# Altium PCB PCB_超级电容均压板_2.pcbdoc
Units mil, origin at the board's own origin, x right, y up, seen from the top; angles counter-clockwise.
Board outline 2770 x 2200 mil, 2 copper layers (Top Layer, Bottom Layer); 57 components, 38 nets, 150 pads, 0 vias.
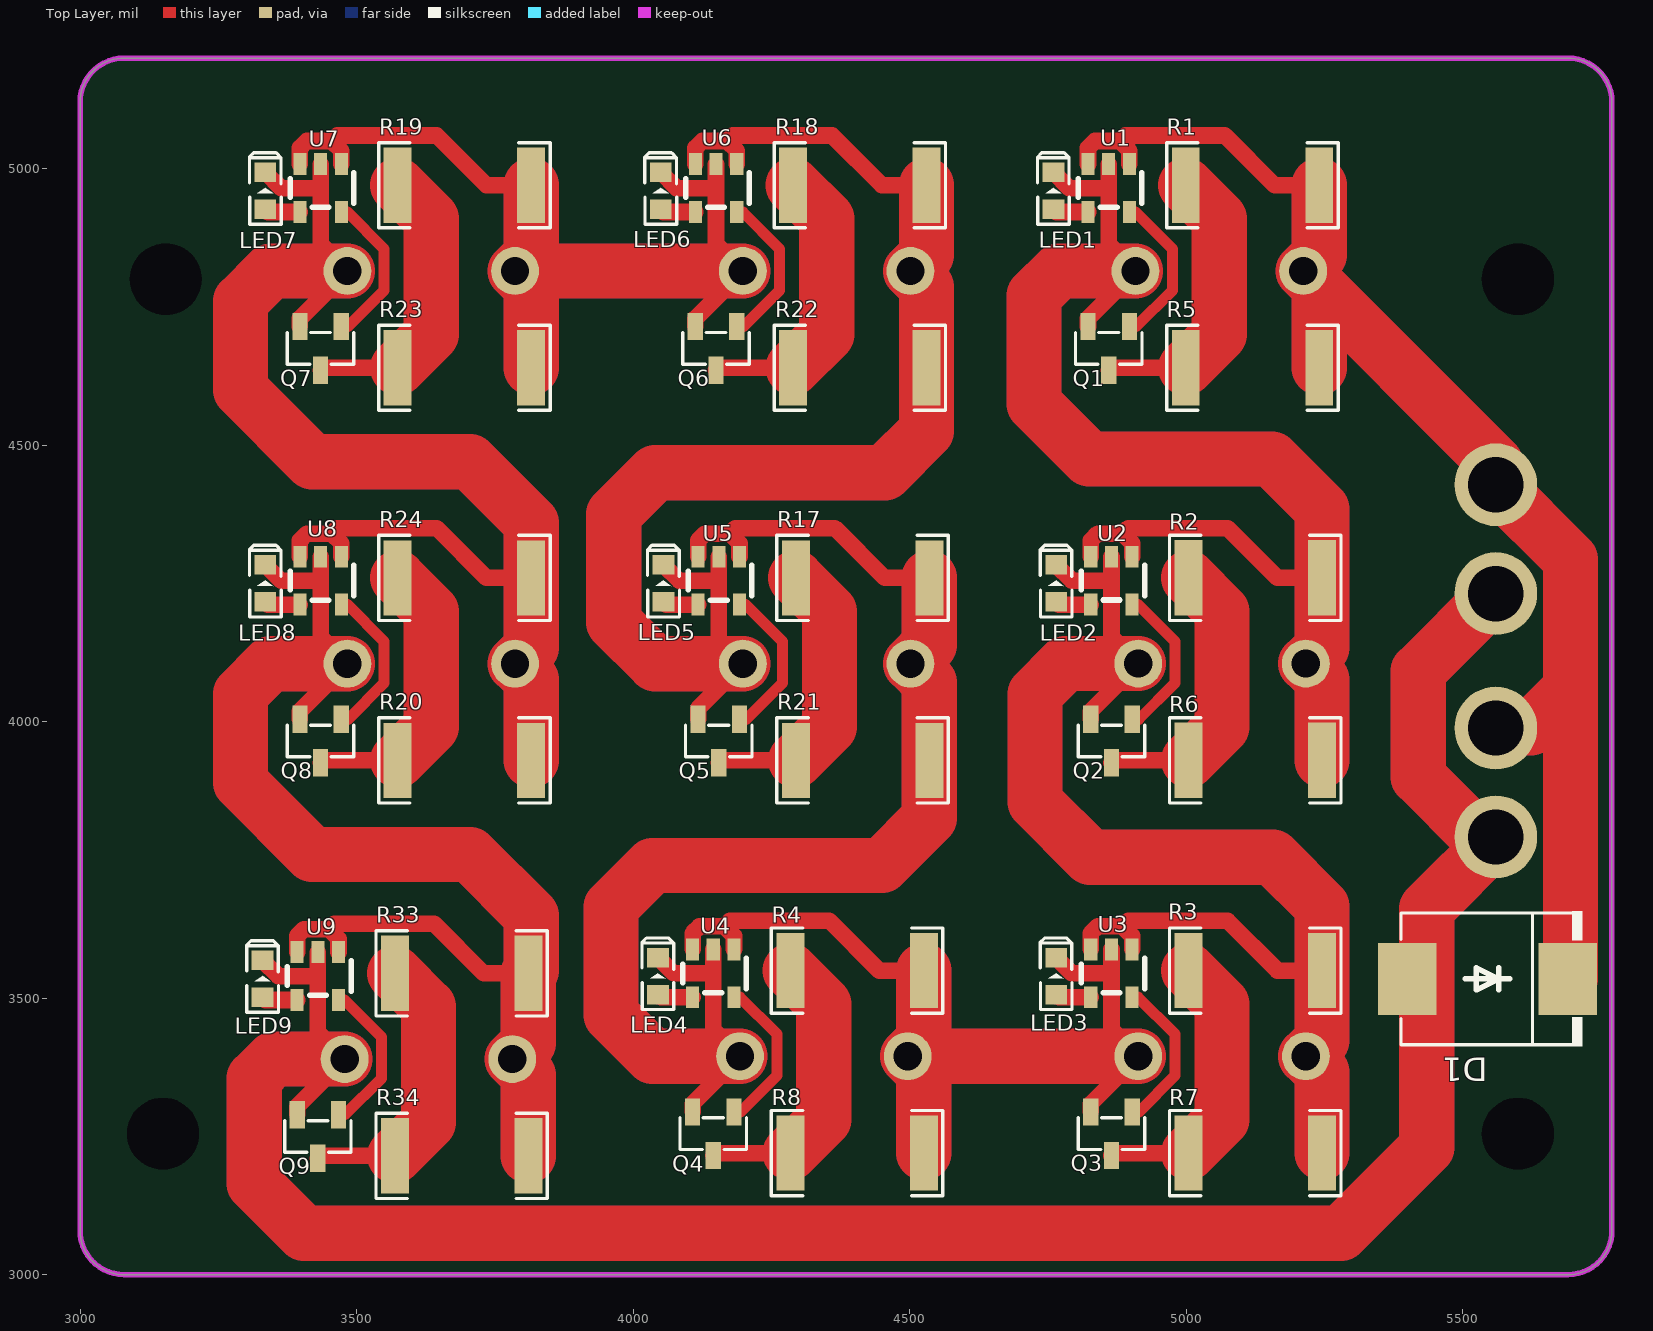
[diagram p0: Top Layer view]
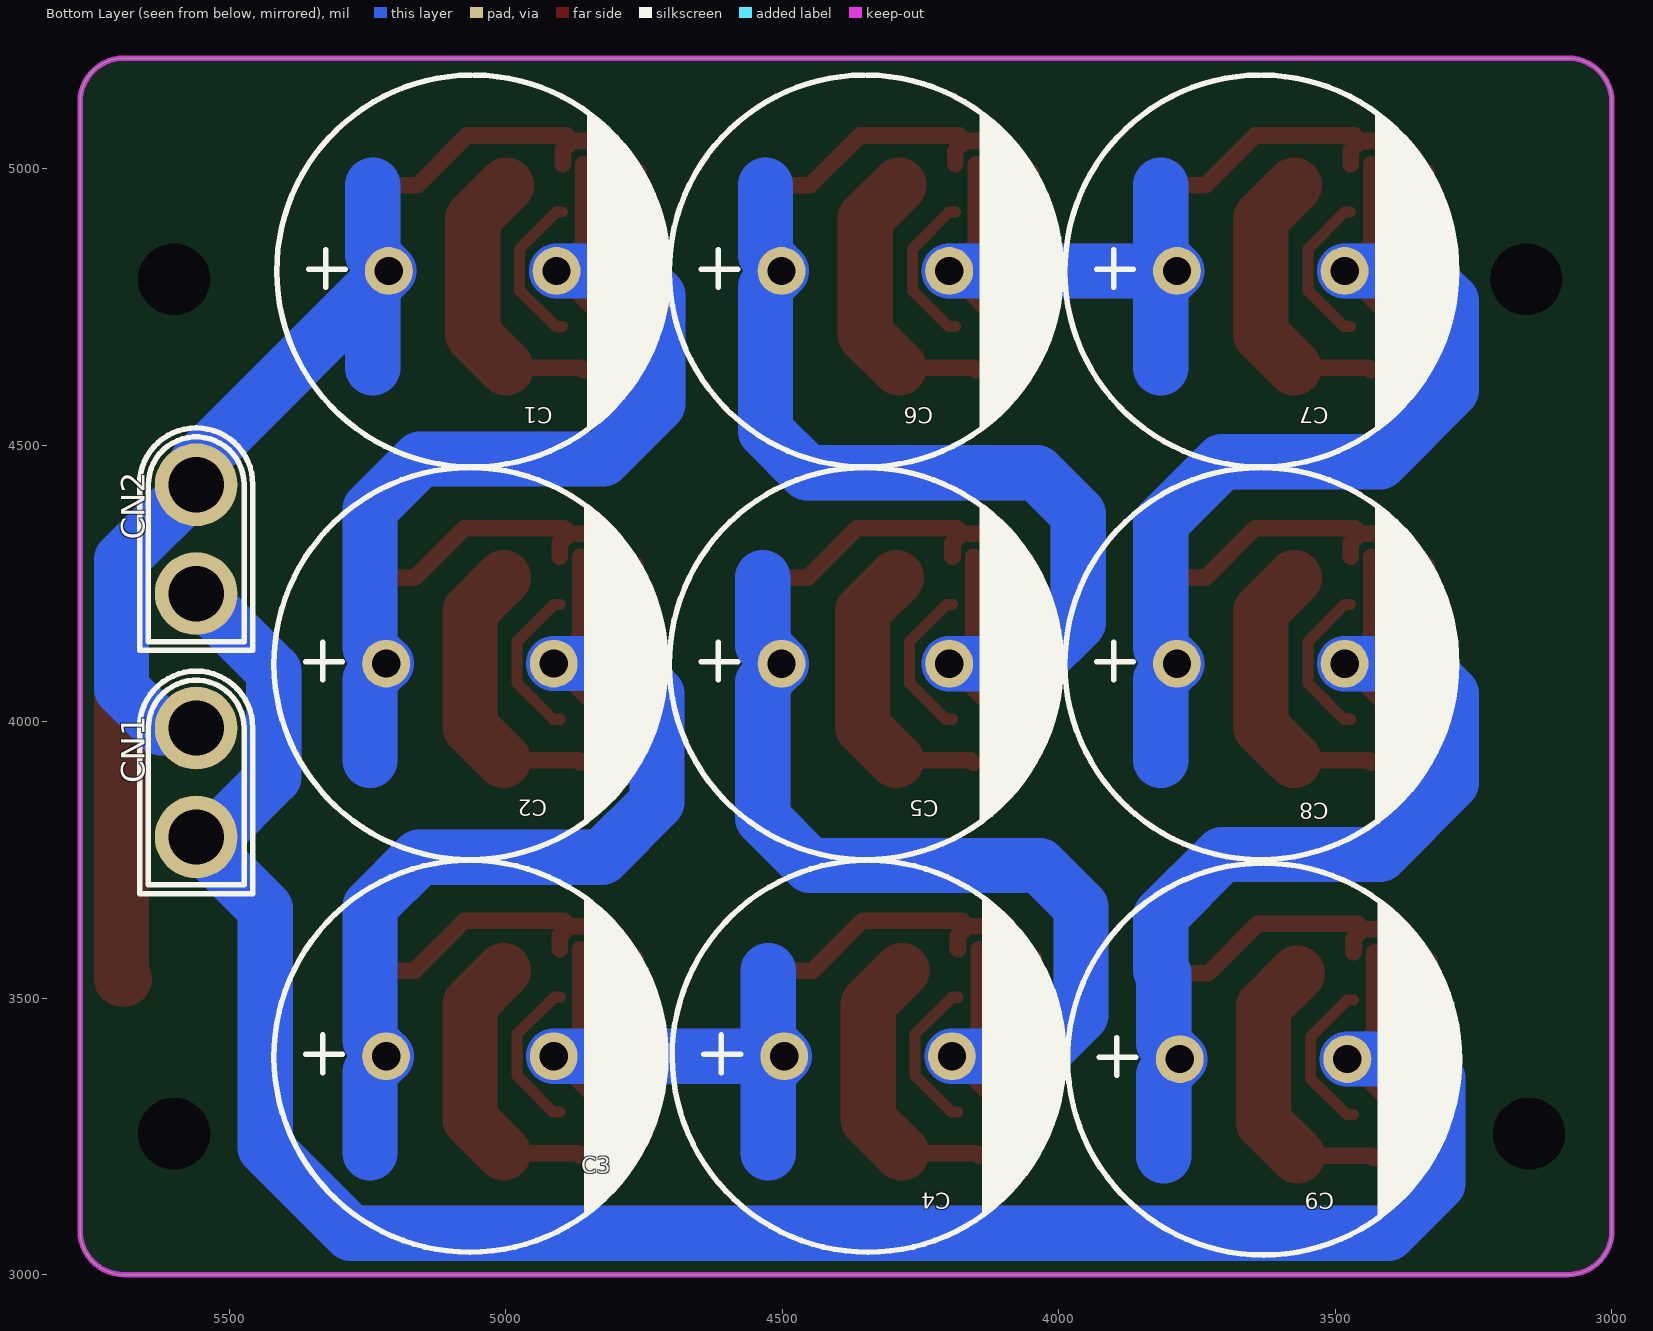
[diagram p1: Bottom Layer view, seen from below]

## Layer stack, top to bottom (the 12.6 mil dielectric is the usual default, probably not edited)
Top Layer: signal copper (thickness not stored)
Dielectric: dielectric 12.6, FR-4, Dk 4.8
Bottom Layer: signal copper (thickness not stored)

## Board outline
3000,5120 cw(c3080,5120) 3080,5200 5690,5200 cw(c5690,5120) 5770,5120 5770,3080 cw(c5690,3080) 5690,3000 3080,3000 cw(c3080,3080) 3000,3080
cut-out: 3215,3255 ccw(c3150,3255) 3085,3255 ccw(c3150,3255)
cut-out: 3220,4800 ccw(c3155,4800) 3090,4800 ccw(c3155,4800)
cut-out: 5665,4800 ccw(c5600,4800) 5535,4800 ccw(c5600,4800)
cut-out: 5665,3255 ccw(c5600,3255) 5535,3255 ccw(c5600,3255)

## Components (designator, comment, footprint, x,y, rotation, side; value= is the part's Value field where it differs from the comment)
C1 "2.7V60F" CAP-TH_BD18.0-P7.70-D0.8-FD 5060,4815 r180 bottom
C2 "2.7V60F" CAP-TH_BD18.0-P7.70-D0.8-FD 5065,4105.05 r180 bottom
C3 "2.7V60F" CAP-TH_BD18.0-P7.70-D0.8-FD 5065,3395 r180 bottom
C4 "2.7V60F" CAP-TH_BD18.0-P7.70-D0.8-FD 4345,3395 r180 bottom
C5 "2.7V60F" CAP-TH_BD18.0-P7.70-D0.8-FD 4350,4105 r180 bottom
C6 "2.7V60F" CAP-TH_BD18.0-P7.70-D0.8-FD 4350,4815 r180 bottom
C7 "2.7V60F" CAP-TH_BD18.0-P7.70-D0.8-FD 3635,4815 r180 bottom
C8 "2.7V60F" CAP-TH_BD18.0-P7.70-D0.8-FD 3635,4105 r180 bottom
C9 "2.7V60F" CAP-TH_BD18.0-P7.70-D0.8-FD 3630,3390 r180 bottom
CN1 "XT30U-M" CONN-TH_XT30U-M 5560,3890 r90 bottom
CN2 "XT30U-M" CONN-TH_XT30U-M 5560,4330 r90 bottom
D1 "5.0SMDJ26A" SMC_L6.9-W5.9-LS7.9-RD 5545,3535 r180 top
LED1 "LED-0603_R" LED0603_RED 4760,4960 r90 top
LED2 "LED-0603_R" LED0603_RED 4765,4250.05 r90 top
LED3 "LED-0603_R" LED0603_RED 4765,3540 r90 top
LED4 "LED-0603_R" LED0603_RED 4045,3540 r90 top
LED5 "LED-0603_R" LED0603_RED 4055,4250 r90 top
LED6 "LED-0603_R" LED0603_RED 4050,4960 r90 top
LED7 "LED-0603_R" LED0603_RED 3335,4960 r90 top
LED8 "LED-0603_R" LED0603_RED 3335,4250 r90 top
LED9 "LED-0603_R" LED0603_RED 3330,3535 r90 top
Q1 "AO3400_C181090" SOT-23-3_L2.9-W1.3-P1.90-LS2.4-BR 4860,4675 r90 top
Q2 "AO3400_C181090" SOT-23-3_L2.9-W1.3-P1.90-LS2.4-BR 4865,3965.05 r90 top
Q3 "AO3400_C181090" SOT-23-3_L2.9-W1.3-P1.90-LS2.4-BR 4865,3255 r90 top
Q4 "AO3400_C181090" SOT-23-3_L2.9-W1.3-P1.90-LS2.4-BR 4145,3255 r90 top
Q5 "AO3400_C181090" SOT-23-3_L2.9-W1.3-P1.90-LS2.4-BR 4155,3965 r90 top
Q6 "AO3400_C181090" SOT-23-3_L2.9-W1.3-P1.90-LS2.4-BR 4150,4675 r90 top
Q7 "AO3400_C181090" SOT-23-3_L2.9-W1.3-P1.90-LS2.4-BR 3435,4675 r90 top
Q8 "AO3400_C181090" SOT-23-3_L2.9-W1.3-P1.90-LS2.4-BR 3435,3965 r90 top
Q9 "AO3400_C181090" SOT-23-3_L2.9-W1.3-P1.90-LS2.4-BR 3430,3250 r90 top
R1 "2Ω" R2512 5120,4970 r0 top
R2 "2Ω" R2512 5125,4260.05 r0 top
R3 "2Ω" R2512 5125,3550 r0 top
R4 "2Ω" R2512 4405,3550 r0 top
R5 "2Ω" R2512 5120,4640 r0 top
R6 "2Ω" R2512 5125,3930.05 r0 top
R7 "2Ω" R2512 5125,3220 r0 top
R8 "2Ω" R2512 4405,3220 r0 top
R17 "2Ω" R2512 4415,4260 r0 top
R18 "2Ω" R2512 4410,4970 r0 top
R19 "2Ω" R2512 3695,4970 r0 top
R20 "2Ω" R2512 3695,3930 r0 top
R21 "2Ω" R2512 4415,3930 r0 top
R22 "2Ω" R2512 4410,4640 r0 top
R23 "2Ω" R2512 3695,4640 r0 top
R24 "2Ω" R2512 3695,4260 r0 top
R33 "2Ω" R2512 3690,3545 r0 top
R34 "2Ω" R2512 3690,3215 r0 top
U1 "BW6101" SOT-23-5_L2.9-W1.6-P0.95-LS2.8-BL 4860,4965 r180 top
U2 "BW6101" SOT-23-5_L2.9-W1.6-P0.95-LS2.8-BL 4865,4255.05 r180 top
U3 "BW6101" SOT-23-5_L2.9-W1.6-P0.95-LS2.8-BL 4865,3545 r180 top
U4 "BW6101" SOT-23-5_L2.9-W1.6-P0.95-LS2.8-BL 4145,3545 r180 top
U5 "BW6101" SOT-23-5_L2.9-W1.6-P0.95-LS2.8-BL 4155,4255 r180 top
U6 "BW6101" SOT-23-5_L2.9-W1.6-P0.95-LS2.8-BL 4150,4965 r180 top
U7 "BW6101" SOT-23-5_L2.9-W1.6-P0.95-LS2.8-BL 3435,4965 r180 top
U8 "BW6101" SOT-23-5_L2.9-W1.6-P0.95-LS2.8-BL 3435,4255 r180 top
U9 "BW6101" SOT-23-5_L2.9-W1.6-P0.95-LS2.8-BL 3430,3540 r180 top

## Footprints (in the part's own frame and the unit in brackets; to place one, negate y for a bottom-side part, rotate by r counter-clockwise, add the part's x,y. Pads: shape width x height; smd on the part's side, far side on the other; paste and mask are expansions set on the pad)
CAP-TH_BD18.0-P7.70-D0.8-FD [mm]
  round 2.2 hole 1.3 paste+0 mask+0.051: 1(-3.85,0) 2(3.85,0)
  silkscreen extent -9,-9 9,9
CONN-TH_XT30U-M [mm]
  round 3.8 hole 2.54 paste+0 mask+0.05: 1(-2.5,0) 2(2.5,0)
  silkscreen extent -5.1,-2.6 5.11,2.6
LED0603_RED [mm]
  rect 0.9x1 smd paste+0 mask+0.051: 1(-0.85,0) 2(0.85,0)
  silkscreen extent -1.54,-0.73 1.75,0.73
R2512 [mil]
  rect 50.49x136.06 smd paste-3937.01 mask+2: 1(-120.72,0) 2(120.72,0)
  silkscreen extent -155,-77 155,77
SMC_L6.9-W5.9-LS7.9-RD [mm]
  rect 2.7x3.3 smd paste+0 mask+0.051: 1(-3.686,0) 2(3.686,0)
  silkscreen extent -4.36,-3.1 3.98,3.1
SOT-23-3_L2.9-W1.3-P1.90-LS2.4-BR [mm]
  rect 1.25x0.7 smd paste+0 mask+0.051: 1(1,-0.95) 2(1,0.95) 3(-1,0)
  silkscreen extent -0.73,-1.53 0.73,1.53
SOT-23-5_L2.9-W1.6-P0.95-LS2.8-BL [mm]
  rect 0.6x1 smd paste+0 mask+0.05: 1(-0.95,-1.1) 2(0,-1.1) 3(0.95,-1.1) 4(0.95,1.1) 5(-0.95,1.1)
  silkscreen extent -1.52,-0.7 1.4,0.89

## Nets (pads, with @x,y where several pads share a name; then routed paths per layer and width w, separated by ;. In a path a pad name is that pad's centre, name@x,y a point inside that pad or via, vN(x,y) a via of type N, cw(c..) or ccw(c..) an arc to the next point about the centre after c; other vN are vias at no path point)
GND: C9.2 CN1.1 CN2.1 D1.2 LED9.2 Q9.2 U9.2 | length 8030
  Top Layer w30: LED9.2 3358.54,3539.92 3430,3539.92 ; Q9.2 3392.6,3304.18 C9.2 3430,3438.43 U9.2
  Top Layer w100: C9.2 3350,3390 3315,3355 3315,3165 3405,3075 5280,3075 5435,3230 5435,3661.57 5565,3791.57 5528.43,3791.57 5420,3900 5420,4091.58 CN2.1
  Bottom Layer w100: C9.2 3350,3390 3315,3355 3315,3165 3405,3075 5280,3075 5435,3230 5435,3661.57 5565,3791.57 5528.43,3791.57 5420,3900 5420,4091.58 CN2.1
LED2_1: LED2.1 U2.4 | length 64.6
  Top Layer w30: LED2.1 4769.84,4211.74 U2.4
LED3_1: LED3.1 U3.4 | length 64.6
  Top Layer w30: LED3.1 4769.85,3501.69 U3.4
LED5_1: LED5.1 U5.4 | length 64.6
  Top Layer w30: LED5.1 4059.84,4211.69 U5.4
LED8_1: LED8.1 U8.4 | length 64.6
  Top Layer w30: LED8.1 3339.84,4211.69 U8.4
Q2_1: Q2.1 U2.5 | length 285
  Top Layer w20: Q2.1 4914.38,4004.42 4980,4070.05 4980,4145.05 4913.31,4211.74 U2.5
Q2_2: C2.2 C3.1 LED2.2 Q2.2 R3.2 R7.2 U2.2 U3.1 U3.3 | length 3948.5
  Top Layer w30: LED2.2 4793.54,4254.97 4865,4254.97 ; U3.3 4827.61,3617.61 4840.01,3630 4885.01,3630 ; Q2.2 4827.6,4019.23 4913.43,4105.05 4865,4153.48 U2.2 ; U3.1 4902.41,3612.61 4885.01,3630 ; R3.2 5165.01,3550 5075.01,3640 4895.01,3640 4885.01,3630
  Top Layer w100: C2.2 4781.65,4105.05 4726.6,4050 4726.6,3855 4826.6,3755 5156.6,3755 5245.73,3665.88 R3.2 ; R7.2 5245.73,3365.86 C3.1 5245.73,3424.15 R3.2
  Bottom Layer w100: C2.2 4781.65,4105.05 4726.6,4050 4726.6,3855 4826.6,3755 5156.6,3755 5245.73,3665.88 5245.72,3550 ; 5245.73,3220 5245.73,3365.86 C3.1 5245.73,3424.15 5245.73,3550
Q2_3: Q2.3 R2.1 R6.1 | length 521.4
  Top Layer w30: Q2.3 4869.38,3930.05 R6.1
  Top Layer w100: R6.1 5065,3990.77 5065,4199.33 R2.1
Q3_1: Q3.1 U3.5 | length 285
  Top Layer w20: Q3.1 4914.38,3294.38 4980.01,3360 4980.01,3435 4913.32,3501.69 U3.5
Q3_3: Q3.3 R3.1 R7.1 | length 521.4
  Top Layer w30: Q3.3 4869.38,3220 R7.1
  Top Layer w100: R7.1 5065.01,3280.72 5065.01,3489.28 R3.1
Q5_1: Q5.1 U5.5 | length 285
  Top Layer w20: Q5.1 4204.37,4004.37 4270,4070 4270,4145 4203.31,4211.69 U5.5
Q5_3: Q5.3 R17.1 R21.1 | length 521.4
  Top Layer w30: Q5.3 4159.37,3930 R21.1
  Top Layer w100: R21.1 4355,3990.72 4355,4199.28 R17.1
Q8_1: Q8.1 U8.5 | length 285
  Top Layer w20: Q8.1 3484.37,4004.37 3550,4070 3550,4145 3483.31,4211.69 U8.5
Q8_2: C8.2 C9.1 LED8.2 Q8.2 R33.2 R34.2 U8.2 U9.1 U9.3 | length 3914.3
  Top Layer w30: LED8.2 3363.54,4254.92 3435,4254.92 ; U9.3 3392.6,3612.6 3405,3625 3450,3625 ; Q8.2 3397.6,4019.18 C8.2 3435,4153.43 U8.2 ; U9.1 3467.4,3607.6 3450,3625 ; R33.2 3730,3545 3640,3635 3460,3635 3450,3625
  Top Layer w100: C8.2 3345,4105 3290,4050 3290,3890 3420,3760 3705,3760 3815.7,3649.3 R33.2@3815.7,3550 ; R34.2 3810.72,3360.86 C9.1 3810.72,3419.15 R33.2
  Bottom Layer w100: C8.2 3345,4105 3290,4050 3290,3890 3420,3760 3705,3760 3815.7,3649.3 3815.7,3550 ; 3810.72,3215 3810.72,3360.86 C9.1 3810.72,3419.15 3810.72,3545
Q8_3: Q8.3 R20.1 R24.1 | length 521.4
  Top Layer w30: Q8.3 3439.37,3930 R20.1
  Top Layer w100: R20.1 3635,3990.72 3635,4199.28 R24.1
R1_1: Q1.3 R1.1 R5.1 | length 521.4
  Top Layer w30: Q1.3 4864.37,4640 R5.1
  Top Layer w100: R5.1 5060,4700.72 5060,4909.28 R1.1
R4_1: Q4.3 R4.1 R8.1 | length 521.4
  Top Layer w30: Q4.3 4149.38,3220 R8.1
  Top Layer w100: R8.1 4345.01,3280.72 4345.01,3489.28 R4.1
R18_1: Q6.3 R18.1 R22.1 | length 521.4
  Top Layer w30: Q6.3 4154.37,4640 R22.1
  Top Layer w100: R22.1 4350,4700.72 4350,4909.28 R18.1
R19_1: Q7.3 R19.1 R23.1 | length 521.4
  Top Layer w30: Q7.3 3439.37,4640 3509.97,4640 R23.1
  Top Layer w100: R23.1 3635,4700.72 3635,4909.28 R19.1
R33_1: Q9.3 R33.1 R34.1 | length 521.4
  Top Layer w30: Q9.3 3434.37,3215 R34.1
  Top Layer w100: R34.1 3630,3275.72 3630,3484.28 R33.1
U1_2: C1.2 C2.1 LED1.2 Q1.2 R2.2 R6.2 U1.2 U2.1 U2.3 | length 3954.5
  Top Layer w30: LED1.2 4788.54,4964.92 4860,4964.92 ; Q1.2 4822.6,4729.18 C1.2 4860,4863.43 U1.2 ; U2.3 4827.6,4327.65 4840,4340.05 4885,4340.05 ; U2.1 4902.4,4322.65 4885,4340.05 ; R2.2 5165,4260.05 5075,4350.05 4895,4350.05 4885,4340.05
  Top Layer w100: C1.2 4770,4815 4725,4770 4725,4575 4825,4475 5155,4475 5245.72,4384.28 5245.72,4260.05 5245.72,4134.2 5216.58,4105.05 5245.72,4075.91 R6.2
  Bottom Layer w100: C1.2 4770,4815 4725,4770 4725,4575 4825,4475 5155,4475 5245.72,4384.28 5245.72,4260.05 5245.72,4134.2 5216.58,4105.05 5245.72,4075.91 5245.72,3930.05
U1_4: LED1.1 U1.4 | length 64.6
  Top Layer w30: LED1.1 4764.84,4921.69 U1.4
U1_5: Q1.1 U1.5 | length 285
  Top Layer w20: Q1.1 4909.4,4714.4 4975,4780 4975,4855 4908.3,4921.7 U1.5
U4_1: C3.2 C4.1 LED3.2 Q3.2 R4.2 R8.2 U3.2 U4.1 U4.3 | length 2546.2
  Top Layer w30: U4.3 4107.61,3617.61 4120.01,3630 4165.01,3630 ; U4.1 4182.41,3612.61 4165.01,3630 ; R4.2 4445.01,3550 4355.01,3640 4175.01,3640 4165.01,3630 ; LED3.2 4793.55,3544.92 4865.01,3544.92 ; Q3.2 4827.61,3309.18 C3.2 4865.01,3443.43 U3.2
  Top Layer w100: R8.2 4525.73,3365.86 C4.1 ; R4.2 4525.73,3424.15 C4.1 ; C3.2 C4.1
  Bottom Layer w100: 4525.73,3220 4525.73,3365.86 C4.1 ; 4525.73,3550 4525.73,3424.15 C4.1 ; C3.2 C4.1
U4_2: C4.2 C5.1 LED4.2 Q4.2 R17.2 R21.2 U4.2 U5.1 U5.3 | length 4132.9
  Top Layer w30: LED4.2 4073.55,3544.92 4145.01,3544.92 ; Q4.2 4107.61,3309.18 C4.2 4145.01,3443.43 U4.2 ; U5.3 4117.6,4327.6 4130,4340 4175,4340 ; U5.1 4192.4,4322.6 4175,4340 ; R17.2 4455,4260 4365,4350 4185,4350 4175,4340
  Top Layer w100: C4.2 4035,3395 3960,3470 3960,3665 4035,3740 4450,3740 4535.72,3825.72 R21.2 4535.72,4070.86 C5.1 4535.72,4139.14 R17.2
  Bottom Layer w100: C4.2 4035,3395 3960,3470 3960,3665 4035,3740 4450,3740 4535.72,3825.72 4535.72,3930 4535.72,4070.86 C5.1 4535.72,4139.14 4535.72,4260
U4_4: LED4.1 U4.4 | length 64.6
  Top Layer w30: LED4.1 4049.85,3501.69 U4.4
U4_5: Q4.1 U4.5 | length 285
  Top Layer w20: Q4.1 4194.38,3294.38 4260.01,3360 4260.01,3435 4193.32,3501.69 U4.5
U6_1: C5.2 C6.1 LED5.2 Q5.2 R18.2 R22.2 U5.2 U6.1 U6.3 | length 4112.2
  Top Layer w30: LED5.2 4083.54,4254.92 4155,4254.92 ; U6.3 4112.6,5037.6 4125,5050 4170,5050 ; Q5.2 4117.6,4024.17 C5.2 4155,4148.43 U5.2 ; U6.1 4187.4,5032.6 4170,5050 ; R18.2 4450,4970 4360,5060 4180,5060 4170,5050
  Top Layer w100: C5.2 4040,4105 3965,4180 3965,4375 4040,4450 4455,4450 4530.7,4525.7 R22.2 4530.72,4785.86 C6.1 4530.72,4844.15 R18.2
  Bottom Layer w100: C5.2 4040,4105 3965,4180 3965,4375 4040,4450 4455,4450 4530.72,4525.72 4530.72,4640 4530.72,4785.86 C6.1 4530.72,4844.15 4530.72,4970
U6_4: LED6.1 U6.4 | length 64.6
  Top Layer w30: LED6.1 4054.84,4921.69 U6.4
U6_5: Q6.1 U6.5 | length 285
  Top Layer w20: Q6.1 4199.4,4714.4 4265,4780 4265,4855 4198.3,4921.7 U6.5
U7_1: C6.2 C7.1 LED6.2 Q6.2 R19.2 R23.2 U6.2 U7.1 U7.3 | length 2536.2
  Top Layer w30: U7.3 3397.6,5037.6 3410,5050 3455,5050 ; U7.1 3472.4,5032.6 3455,5050 ; R19.2 3735,4970 3645,5060 3465,5060 3455,5050 ; LED6.2 4078.54,4964.92 4150,4964.92 ; Q6.2 4112.6,4729.18 C6.2 4150,4863.43 U6.2
  Top Layer w100: R23.2 3815.72,4785.86 C7.1 ; R19.2 3815.72,4844.15 C7.1 ; C6.2 C7.1
  Bottom Layer w100: 3815.72,4640 3815.72,4785.86 C7.1 ; 3815.72,4970 3815.72,4844.15 C7.1 ; C6.2 C7.1
U7_2: C7.2 C8.1 LED7.2 Q7.2 R20.2 R24.2 U7.2 U8.1 U8.3 | length 3914.3
  Top Layer w30: LED7.2 3363.54,4964.92 3435,4964.92 ; U8.3 3397.6,4327.6 3410,4340 3455,4340 ; Q7.2 3397.6,4729.18 C7.2 3435,4863.43 U7.2 ; U8.1 3472.4,4322.6 3455,4340 ; R24.2 3735,4260 3645,4350 3465,4350 3455,4340
  Top Layer w100: C7.2 3345,4815 3290,4760 3290,4600 3420,4470 3705,4470 3815.7,4359.3 R24.2 3815.72,4134.15 C8.1 3815.72,4075.86 R20.2
  Bottom Layer w100: C7.2 3345,4815 3290,4760 3290,4600 3420,4470 3705,4470 3815.72,4359.28 3815.72,4260 3815.72,4134.15 C8.1 3815.72,4075.86 3815.72,3930
U7_4: LED7.1 U7.4 | length 64.6
  Top Layer w30: LED7.1 3339.84,4921.69 U7.4
U7_5: Q7.1 U7.5 | length 285
  Top Layer w20: Q7.1 3484.4,4714.4 3550,4780 3550,4855 3483.3,4921.7 U7.5
U9_4: LED9.1 U9.4 | length 64.6
  Top Layer w30: LED9.1 3334.85,3496.69 U9.4
U9_5: Q9.1 U9.5 | length 285
  Top Layer w20: Q9.1 3479.4,3289.4 3545,3355 3545,3430 3478.3,3496.7 U9.5
VCC: C1.1 CN1.2 CN2.2 D1.1 R1.2 R5.2 U1.1 U1.3 | length 4010.8
  Top Layer w30: U1.3 4822.6,5037.6 4835,5050 4880,5050 ; U1.1 4897.4,5032.6 4880,5050 ; R1.2 5160,4970 5070,5060 4890,5060 4880,5050
  Top Layer w100: R5.2 5240.72,4785.86 C1.1 ; R1.2 5240.72,4844.15 C1.1 ; CN1.2@5565,3988.42 5623.42,3988.42 5695,4060 ; D1.1 5695,3535 5695,4060 ; C1.1 5560,4466.58 CN2.2 5695,4293.43 5695,4060
  Bottom Layer w100: 5240.72,4640 5240.72,4785.86 C1.1 ; 5240.72,4970 5240.72,4844.15 C1.1 ; CN1.2@5565,3988.42 5623.41,3988.42 5695,4060.01 5695,4293.43 CN2.2 5560,4466.58 C1.1
"": 

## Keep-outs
Board Outline Layer:
  the board outline again, w10

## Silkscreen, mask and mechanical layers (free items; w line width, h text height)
Mechanical Layer:
  circle w0.2 net "": c3150,3255 r65
  circle w0.2 net "": c3155,4800 r65
  circle w0.2 net "": c5600,4800 r65
  circle w0.2 net "": c5600,3255 r65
